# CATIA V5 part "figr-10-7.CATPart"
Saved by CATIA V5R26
Part number: Part1
Bounding box of the stored display mesh (mm): x -9.616 to 10, y -9.533 to 9.835, z 0 to 10
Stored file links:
  D:\_Deepak\CATIA\CATIA V5-6R2016_Deepak\Resources\Part files\Partfiles\c10_catia_v5_6r2016_prt\figr-10-7.CATPart
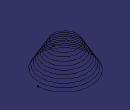
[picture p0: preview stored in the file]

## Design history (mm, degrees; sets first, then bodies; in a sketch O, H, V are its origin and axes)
Set1
  Helix1: Direction {line stored without definition}, RefPoint {point type Coord, X 10, Y 0, Z 0}, Pitch 1, Height 10, TaperAngle 30
Body1 (main body)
